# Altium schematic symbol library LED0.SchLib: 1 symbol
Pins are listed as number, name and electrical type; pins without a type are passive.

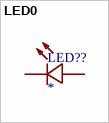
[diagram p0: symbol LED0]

## LED0
designator LED??
footprint LED1206-R-RD
pins: 1 A, 2 K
